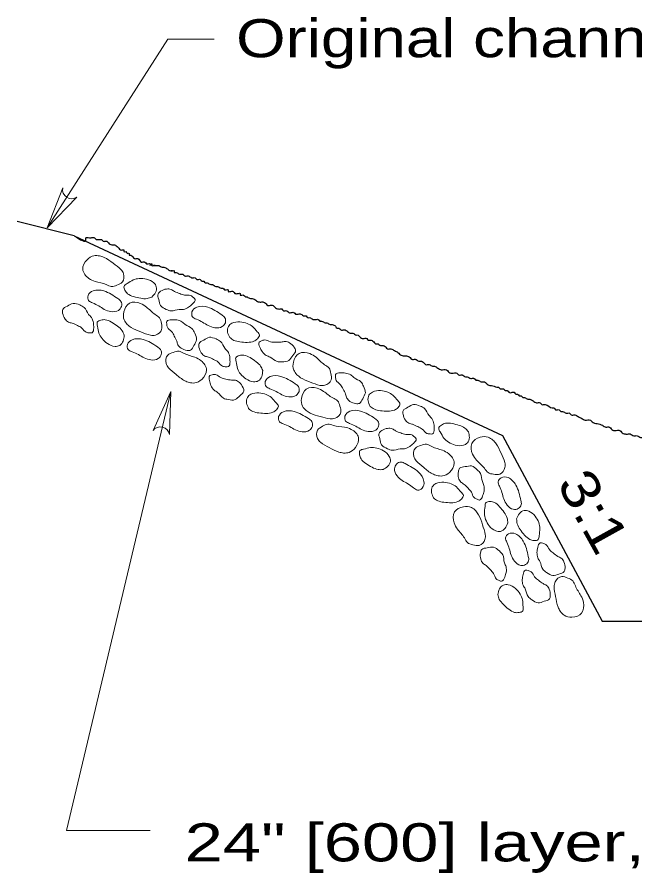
# Model space of a CAD drawing. Extents: x 1043.1 to 1101.1, y 672.4 to 716.4.
# Drawn here: x 1055.748 to 1058.344, y 697.399 to 700.994 of the extents above; entities that cross this region are included whole.
import ezdxf

# ---------------------------------------------------------------- set-up
doc = ezdxf.new("R2010")
doc.units = 0
doc.header["$LTSCALE"] = 0.064
doc.layers.add('1', color=7, linetype='Continuous', lineweight=13)

msp = doc.modelspace()

# ---------------------------------------------------------------- linework, layer by layer
at = {"layer": '1', "lineweight": 25}
for p, q in [((1055.98842, 700.07575), (1055.7485, 700.13575)), ((1055.98842, 700.07575), (1057.7875, 699.23625)), ((1057.7875, 699.23625), (1058.20733, 698.45675)), ((1058.20733, 698.45675), (1060.30633, 698.45675))]:
    msp.add_line(p, q, dxfattribs=at)
at = {"layer": '1'}
for points in [[(1055.87483, 700.10833), (1056.3815, 700.90108), (1056.57592, 700.90108)], [(1055.99958, 700.23808), (1055.87483, 700.10833), (1055.94008, 700.27608), (1055.94017, 700.276)], [(1056.39492, 699.42058), (1055.95592, 697.57708), (1056.3075, 697.57708)], [(1056.31975, 699.25708), (1056.39492, 699.42058), (1056.38842, 699.24067), (1056.38833, 699.24075)]]:
    msp.add_lwpolyline(points, dxfattribs=at)
for centre, start, end in [((1055.97764, 700.26913), 169.50421, 305.33034), ((1056.35067, 699.23493), 8.69329, 144.51942)]:
    msp.add_arc(centre, 0.03811, start, end, dxfattribs=at)
at = {"layer": '1', "lineweight": 25}
for points in [[(1055.98842, 700.07575), (1056.03742, 700.05975), (1056.03742, 700.067), (1056.052, 700.067), (1056.05933, 700.067), (1056.07383, 700.067), (1056.08108, 700.05975), (1056.08842, 700.05975), (1056.09575, 700.05975), (1056.103, 700.05975), (1056.11033, 700.05242), (1056.12492, 700.05242), (1056.13208, 700.04508), (1056.14658, 700.03783), (1056.15392, 700.03783), (1056.1685, 700.0305), (1056.17583, 700.02325), (1056.18308, 700.01592), (1056.19042, 700.01592), (1056.19758, 700.01592), (1056.19758, 700.00875), (1056.20492, 700.00875), (1056.21225, 700.00142), (1056.2195, 700.00142), (1056.2195, 699.99408), (1056.22683, 699.99408), (1056.23408, 699.98683), (1056.24142, 699.9795), (1056.24875, 699.9795), (1056.256, 699.9795), (1056.26325, 699.97233), (1056.2705, 699.965), (1056.28508, 699.965), (1056.29242, 699.95775), (1056.29975, 699.95775), (1056.307, 699.95775), (1056.307, 699.95042), (1056.31433, 699.95775), (1056.31433, 699.95042), (1056.31433, 699.95775), (1056.31433, 699.95042), (1056.32158, 699.95042), (1056.32883, 699.95042), (1056.32158, 699.95042), (1056.32883, 699.95042), (1056.336, 699.95042), (1056.34333, 699.95042), (1056.35792, 699.94308), (1056.36525, 699.94308), (1056.37983, 699.93583), (1056.39433, 699.9285), (1056.40158, 699.9285), (1056.39433, 699.9285), (1056.40158, 699.9285), (1056.40892, 699.9285), (1056.40892, 699.92125), (1056.41625, 699.92125), (1056.43083, 699.91392), (1056.44542, 699.91392), (1056.45258, 699.90658), (1056.46725, 699.90658), (1056.48183, 699.89933), (1056.48908, 699.89933), (1056.49642, 699.89933), (1056.50375, 699.892), (1056.51092, 699.892), (1056.51825, 699.892), (1056.5255, 699.88475), (1056.53283, 699.88475), (1056.54008, 699.87742), (1056.54733, 699.87742), (1056.56192, 699.87008), (1056.56925, 699.87008), (1056.58375, 699.86283), (1056.591, 699.86283), (1056.60558, 699.8555), (1056.61292, 699.8555), (1056.62025, 699.84825), (1056.6275, 699.84825), (1056.63475, 699.84825), (1056.63475, 699.84092), (1056.642, 699.84092), (1056.65658, 699.84092), (1056.66392, 699.83358), (1056.6785, 699.83358), (1056.68583, 699.83358), (1056.68583, 699.82633), (1056.69308, 699.82633), (1056.70033, 699.82633), (1056.70758, 699.81908), (1056.71492, 699.81908)], [(1056.71492, 699.81908), (1056.7295, 699.81183), (1056.73683, 699.81183), (1056.75133, 699.8045), (1056.76583, 699.79725), (1056.78042, 699.79725), (1056.795, 699.78992), (1056.80233, 699.78258), (1056.80958, 699.78258), (1056.82408, 699.78258), (1056.83142, 699.77533), (1056.846, 699.768), (1056.85333, 699.768), (1056.86058, 699.768), (1056.86792, 699.76075), (1056.87525, 699.76075), (1056.88242, 699.76075), (1056.88975, 699.75342), (1056.90433, 699.75342), (1056.91158, 699.75342), (1056.91892, 699.74608), (1056.92625, 699.74608), (1056.94075, 699.74608), (1056.95525, 699.73883), (1056.9625, 699.73883), (1056.96983, 699.7315), (1056.97708, 699.7315), (1056.99175, 699.72425), (1057.00625, 699.72425), (1057.0135, 699.72425), (1057.02083, 699.71692), (1057.02808, 699.71692), (1057.04275, 699.70958), (1057.05, 699.70958), (1057.06458, 699.70233), (1057.07183, 699.70233), (1057.08642, 699.695), (1057.09375, 699.68775), (1057.101, 699.68775), (1057.10833, 699.68042), (1057.12292, 699.68042), (1057.13742, 699.67308), (1057.15192, 699.66583), (1057.15925, 699.66583), (1057.17383, 699.6585), (1057.18108, 699.6585), (1057.18842, 699.65125), (1057.20292, 699.64392), (1057.2175, 699.64392), (1057.22483, 699.63675), (1057.23208, 699.63675), (1057.24675, 699.62942), (1057.25392, 699.62208), (1057.26125, 699.62208), (1057.27583, 699.61483), (1057.28308, 699.61483), (1057.29775, 699.6075), (1057.305, 699.60025), (1057.3195, 699.60025), (1057.33408, 699.59292), (1057.34858, 699.58558), (1057.35592, 699.57833), (1057.3705, 699.571), (1057.385, 699.571), (1057.39958, 699.56375), (1057.40692, 699.55642), (1057.4215, 699.55642), (1057.43608, 699.54908), (1057.44333, 699.54908), (1057.45792, 699.54183), (1057.46525, 699.5345), (1057.47983, 699.5345), (1057.49442, 699.52725), (1057.50175, 699.52725), (1057.51625, 699.51992), (1057.53083, 699.51258), (1057.55258, 699.51258), (1057.55992, 699.50533), (1057.57442, 699.498), (1057.59633, 699.498), (1057.60358, 699.49075), (1057.61825, 699.49075), (1057.63275, 699.48342), (1057.64, 699.48342), (1057.65458, 699.47625), (1057.66925, 699.47625), (1057.6765, 699.46892), (1057.68383, 699.46892), (1057.69833, 699.46158), (1057.71292, 699.46158), (1057.72025, 699.45433)], [(1057.72025, 699.45433), (1057.73483, 699.447), (1057.74208, 699.447), (1057.76383, 699.43975), (1057.77108, 699.43975), (1057.77842, 699.43242), (1057.793, 699.43242), (1057.80033, 699.42508), (1057.80758, 699.42508), (1057.81483, 699.41783), (1057.82942, 699.41783), (1057.83675, 699.41783), (1057.844, 699.4105), (1057.85133, 699.4105), (1057.85858, 699.40325), (1057.86592, 699.40325), (1057.87325, 699.39592), (1057.88042, 699.39592), (1057.895, 699.38858), (1057.90233, 699.38858), (1057.91692, 699.38133), (1057.9315, 699.374), (1057.946, 699.374), (1057.95333, 699.36675), (1057.96783, 699.36675), (1057.997, 699.35208), (1058.00425, 699.35208), (1058.0115, 699.34483), (1058.02608, 699.34483), (1058.03342, 699.3375), (1058.04075, 699.3375), (1058.05533, 699.33025), (1058.06983, 699.33025), (1058.07708, 699.32292), (1058.09175, 699.32292), (1058.10633, 699.31575), (1058.12092, 699.30842), (1058.13542, 699.30108), (1058.15725, 699.30108), (1058.1645, 699.29383), (1058.18633, 699.2865), (1058.20825, 699.27925), (1058.22283, 699.27192), (1058.23742, 699.27192), (1058.24475, 699.26458), (1058.25925, 699.25733), (1058.28108, 699.25733), (1058.28842, 699.25), (1058.303, 699.24275), (1058.3175, 699.24275), (1058.32483, 699.24275), (1058.33942, 699.23542), (1058.354, 699.23542), (1058.3685, 699.22808), (1058.37575, 699.22808), (1058.39033, 699.22083), (1058.40492, 699.22083), (1058.4195, 699.2135), (1058.44133, 699.20625), (1058.45592, 699.20625), (1058.4705, 699.19892), (1058.48508, 699.19892), (1058.49242, 699.19892), (1058.50692, 699.19158), (1058.5215, 699.18433), (1058.53608, 699.18433), (1058.55075, 699.177), (1058.56508, 699.177), (1058.57975, 699.16975), (1058.587, 699.16242), (1058.60158, 699.16242), (1058.60892, 699.15508), (1058.62342, 699.15508), (1058.63075, 699.14792), (1058.64533, 699.14792), (1058.65258, 699.14058), (1058.66725, 699.14058), (1058.6745, 699.13333), (1058.689, 699.13333), (1058.70358, 699.126), (1058.71092, 699.126), (1058.7255, 699.11875), (1058.74008, 699.11142), (1058.74733, 699.11142), (1058.76183, 699.10408), (1058.76908, 699.10408), (1058.78375, 699.09683), (1058.79833, 699.0895), (1058.80558, 699.0895), (1058.82008, 699.08225), (1058.83475, 699.08225)]]:
    msp.add_spline(points, degree=3, dxfattribs=at)
at = {"layer": '1'}
for points in [[(1056.09475, 699.99083), (1056.07133, 699.99133), (1056.04258, 699.97458), (1056.02442, 699.93425), (1056.04983, 699.89658), (1056.07708, 699.8835), (1056.12242, 699.87025), (1056.14442, 699.86208), (1056.16808, 699.868), (1056.19092, 699.88125), (1056.19575, 699.91608), (1056.18492, 699.93342), (1056.1515, 699.96008), (1056.114, 699.98433), (1056.09475, 699.99083)], [(1056.31458, 699.818), (1056.29475, 699.8115), (1056.26825, 699.81292), (1056.238, 699.81975), (1056.21292, 699.83208), (1056.2015, 699.84692), (1056.198, 699.86408), (1056.21075, 699.87442), (1056.23658, 699.89), (1056.2615, 699.89583), (1056.2925, 699.89333), (1056.323, 699.878), (1056.33342, 699.86083), (1056.32983, 699.83742), (1056.31458, 699.818)], [(1056.115, 699.76625), (1056.143, 699.757), (1056.17408, 699.762), (1056.18708, 699.77858), (1056.18492, 699.79925), (1056.17192, 699.81125), (1056.11292, 699.84342), (1056.0675, 699.84408), (1056.04675, 699.82433), (1056.049, 699.80308), (1056.06533, 699.79342), (1056.115, 699.76625)], [(1056.46933, 699.775), (1056.48558, 699.78883), (1056.49608, 699.80742), (1056.48933, 699.8155), (1056.478, 699.82433), (1056.45242, 699.82592), (1056.43175, 699.83233), (1056.40983, 699.84142), (1056.39542, 699.85), (1056.37633, 699.85175), (1056.3515, 699.84208), (1056.34083, 699.83175), (1056.3435, 699.80775), (1056.35133, 699.78208), (1056.3755, 699.76633), (1056.39583, 699.75975), (1056.4295, 699.766), (1056.44742, 699.76633), (1056.46933, 699.775)], [(1056.06933, 699.71), (1056.07033, 699.68875), (1056.06383, 699.66833), (1056.05325, 699.66775), (1056.03908, 699.67), (1056.02042, 699.68758), (1056.00158, 699.69842), (1055.98, 699.70825), (1055.96392, 699.71292), (1055.94975, 699.72575), (1055.93983, 699.75042), (1055.94008, 699.76533), (1055.95958, 699.77975), (1055.98358, 699.7915), (1056.01175, 699.78458), (1056.03033, 699.77425), (1056.04875, 699.74533), (1056.06075, 699.732), (1056.06933, 699.71)], [(1056.21158, 699.70275), (1056.19858, 699.72208), (1056.19708, 699.75533), (1056.22125, 699.79242), (1056.26658, 699.79142), (1056.2925, 699.77558), (1056.32825, 699.74475), (1056.34683, 699.73042), (1056.35475, 699.70733), (1056.35592, 699.681), (1056.32933, 699.65808), (1056.30892, 699.65783), (1056.26833, 699.6715), (1056.2275, 699.69008), (1056.21158, 699.70275)], [(1056.5515, 699.69792), (1056.57958, 699.68875), (1056.61075, 699.69375), (1056.62375, 699.71033), (1056.6215, 699.73092), (1056.6085, 699.74292), (1056.54942, 699.77525), (1056.50408, 699.77592), (1056.48333, 699.75608), (1056.48558, 699.73483), (1056.50192, 699.72508), (1056.5515, 699.69792)], [(1056.19833, 699.65758), (1056.18958, 699.67675), (1056.17058, 699.69508), (1056.14508, 699.71275), (1056.119, 699.72283), (1056.10042, 699.72108), (1056.08542, 699.712), (1056.0865, 699.69558), (1056.09258, 699.666), (1056.10525, 699.64392), (1056.128, 699.62283), (1056.15992, 699.61083), (1056.17958, 699.61483), (1056.19433, 699.63333), (1056.19833, 699.65758)], [(1056.419, 699.72225), (1056.39775, 699.72275), (1056.3775, 699.71583), (1056.37708, 699.70508), (1056.37983, 699.69108), (1056.39783, 699.67292), (1056.40908, 699.65433), (1056.41942, 699.63308), (1056.4245, 699.61708), (1056.43775, 699.60325), (1056.46258, 699.59392), (1056.4775, 699.59458), (1056.4915, 699.61442), (1056.50258, 699.63875), (1056.495, 699.6665), (1056.48425, 699.68492), (1056.45483, 699.70258), (1056.44125, 699.71425), (1056.419, 699.72225)], [(1056.642, 699.648), (1056.65925, 699.63608), (1056.68492, 699.62983), (1056.71583, 699.62758), (1056.7435, 699.63225), (1056.75858, 699.64308), (1056.76692, 699.65842), (1056.75775, 699.672), (1056.7375, 699.69442), (1056.71542, 699.70725), (1056.685, 699.71383), (1056.65142, 699.70792), (1056.63642, 699.6945), (1056.63308, 699.67108), (1056.642, 699.648)], [(1056.28233, 699.56233), (1056.31075, 699.55392), (1056.34158, 699.55992), (1056.35408, 699.57683), (1056.35133, 699.59733), (1056.338, 699.60892), (1056.278, 699.63958), (1056.23258, 699.63883), (1056.21242, 699.6185), (1056.21533, 699.59733), (1056.23192, 699.58808), (1056.28233, 699.56233)], [(1056.64208, 699.56733), (1056.64308, 699.546), (1056.63658, 699.52558), (1056.626, 699.525), (1056.61192, 699.52733), (1056.59325, 699.54492), (1056.57442, 699.55575), (1056.55283, 699.5655), (1056.53683, 699.57025), (1056.52258, 699.583), (1056.51275, 699.60775), (1056.513, 699.62258), (1056.5325, 699.637), (1056.55642, 699.64883), (1056.5845, 699.64192), (1056.60308, 699.6315), (1056.6215, 699.60258), (1056.6335, 699.58933), (1056.64208, 699.56733)], [(1056.77825, 699.58883), (1056.76825, 699.60775), (1056.76533, 699.62892), (1056.77475, 699.634), (1056.78842, 699.63792), (1056.81283, 699.62992), (1056.83442, 699.62825), (1056.85808, 699.6285), (1056.87475, 699.63108), (1056.89308, 699.62558), (1056.9125, 699.6075), (1056.91858, 699.59392), (1056.90708, 699.5725), (1056.89042, 699.55158), (1056.862, 699.54592), (1056.84075, 699.54733), (1056.81183, 699.56575), (1056.79533, 699.57258), (1056.77825, 699.58883)], [(1056.47158, 699.45883), (1056.49492, 699.45708), (1056.5245, 699.47233), (1056.54475, 699.5115), (1056.5215, 699.5505), (1056.495, 699.56508), (1056.45042, 699.58083), (1056.42883, 699.59008), (1056.40483, 699.58542), (1056.38133, 699.5735), (1056.37458, 699.53892), (1056.3845, 699.521), (1056.4165, 699.49258), (1056.45275, 699.4665), (1056.47158, 699.45883)], [(1056.7805, 699.50883), (1056.77183, 699.52792), (1056.75283, 699.54633), (1056.72742, 699.56392), (1056.70125, 699.574), (1056.68258, 699.57233), (1056.66758, 699.56325), (1056.66875, 699.54683), (1056.67483, 699.51725), (1056.68742, 699.495), (1056.71025, 699.474), (1056.74208, 699.462), (1056.76183, 699.466), (1056.7765, 699.48442), (1056.7805, 699.50883)], [(1056.92392, 699.49183), (1056.91092, 699.51125), (1056.90942, 699.54442), (1056.9335, 699.5815), (1056.97883, 699.5805), (1057.00475, 699.56475), (1057.04042, 699.53383), (1057.05908, 699.5195), (1057.067, 699.49642), (1057.06825, 699.47025), (1057.0415, 699.44733), (1057.02108, 699.447), (1056.9805, 699.46075), (1056.93975, 699.47933), (1056.92392, 699.49183)], [(1056.56258, 699.44675), (1056.55675, 699.46725), (1056.55833, 699.48842), (1056.5685, 699.4915), (1056.58283, 699.4925), (1056.60492, 699.47975), (1056.62575, 699.47358), (1056.649, 699.469), (1056.66575, 699.46825), (1056.68258, 699.459), (1056.69792, 699.43725), (1056.701, 699.42275), (1056.68542, 699.40408), (1056.66475, 699.38708), (1056.63583, 699.38742), (1056.61533, 699.39325), (1056.59075, 699.41708), (1056.576, 699.42733), (1056.56258, 699.44675)], [(1057.12825, 699.49892), (1057.10692, 699.49942), (1057.08675, 699.4925), (1057.08633, 699.48183), (1057.089, 699.46792), (1057.107, 699.44975), (1057.11833, 699.43108), (1057.12858, 699.40983), (1057.13375, 699.39383), (1057.14683, 699.37992), (1057.17175, 699.37058), (1057.18658, 699.37133), (1057.20058, 699.39108), (1057.21175, 699.41542), (1057.20408, 699.44333), (1057.19333, 699.46175), (1057.16392, 699.47942), (1057.15033, 699.49092), (1057.12825, 699.49892)], [(1056.86142, 699.40725), (1056.88983, 699.39883), (1056.92083, 699.40483), (1056.93333, 699.42175), (1056.9305, 699.44225), (1056.91708, 699.45383), (1056.85708, 699.48442), (1056.81175, 699.48383), (1056.7915, 699.46342), (1056.79442, 699.44225), (1056.811, 699.433), (1056.86142, 699.40725)], [(1056.96292, 699.34133), (1056.948, 699.35942), (1056.94342, 699.39242), (1056.96358, 699.43158), (1057.00892, 699.435), (1057.03625, 699.42192), (1057.07483, 699.3945), (1057.09483, 699.38225), (1057.10492, 699.35992), (1057.10858, 699.33392), (1057.08433, 699.30858), (1057.064, 699.30633), (1057.02233, 699.31583), (1056.97992, 699.33042), (1056.96292, 699.34133)], [(1057.23242, 699.35892), (1057.24958, 699.34692), (1057.27533, 699.34058), (1057.30625, 699.33842), (1057.33392, 699.343), (1057.349, 699.35392), (1057.35733, 699.36933), (1057.34808, 699.38292), (1057.32792, 699.40533), (1057.30583, 699.41808), (1057.27542, 699.42475), (1057.24183, 699.41883), (1057.22683, 699.40542), (1057.2235, 699.382), (1057.23242, 699.35892)], [(1056.7215, 699.34958), (1056.73858, 699.33758), (1056.76433, 699.33133), (1056.79525, 699.32908), (1056.82292, 699.33375), (1056.83808, 699.34458), (1056.84642, 699.36), (1056.83725, 699.37358), (1056.81692, 699.396), (1056.79483, 699.40883), (1056.76442, 699.41542), (1056.73092, 699.4095), (1056.71592, 699.39608), (1056.71258, 699.37275), (1056.7215, 699.34958)], [(1057.49992, 699.28525), (1057.50092, 699.26392), (1057.49442, 699.2435), (1057.48383, 699.24292), (1057.46975, 699.24525), (1057.451, 699.26283), (1057.43225, 699.27358), (1057.41058, 699.28342), (1057.3945, 699.28808), (1057.38033, 699.30092), (1057.37042, 699.3255), (1057.37075, 699.34042), (1057.39025, 699.35483), (1057.41425, 699.36658), (1057.44233, 699.35975), (1057.46092, 699.34933), (1057.47933, 699.32042), (1057.49133, 699.30725), (1057.49992, 699.28525)], [(1056.91783, 699.26025), (1056.94608, 699.252), (1056.977, 699.25825), (1056.98942, 699.27533), (1056.98642, 699.29583), (1056.97292, 699.30725), (1056.91275, 699.33733), (1056.86742, 699.33625), (1056.84742, 699.31575), (1056.85042, 699.2945), (1056.86708, 699.2855), (1056.91783, 699.26025)], [(1057.19583, 699.2615), (1057.22425, 699.25308), (1057.25525, 699.25908), (1057.26775, 699.276), (1057.26492, 699.2965), (1057.2515, 699.30808), (1057.1915, 699.33875), (1057.14625, 699.338), (1057.126, 699.31758), (1057.12892, 699.2965), (1057.14542, 699.28733), (1057.19583, 699.2615)], [(1057.12058, 699.16275), (1057.14375, 699.16533), (1057.17008, 699.18575), (1057.18283, 699.228), (1057.15258, 699.262), (1057.124, 699.2715), (1057.07733, 699.27883), (1057.05433, 699.28392), (1057.0315, 699.27492), (1057.01075, 699.25883), (1057.0105, 699.22358), (1057.0235, 699.20783), (1057.06025, 699.18583), (1057.10075, 699.16675), (1057.12058, 699.16275)], [(1057.64458, 699.25233), (1057.63, 699.26742), (1057.60608, 699.27858), (1057.57625, 699.28683), (1057.54808, 699.28775), (1057.53125, 699.28), (1057.52, 699.26658), (1057.52642, 699.25142), (1057.54192, 699.2255), (1057.561, 699.20858), (1057.5895, 699.19625), (1057.62358, 699.19542), (1057.64092, 699.20558), (1057.64875, 699.22792), (1057.64458, 699.25233)], [(1057.39808, 699.18958), (1057.41442, 699.20342), (1057.42492, 699.222), (1057.41808, 699.23025), (1057.40683, 699.239), (1057.38125, 699.24058), (1057.3605, 699.247), (1057.33875, 699.25608), (1057.32433, 699.26475), (1057.30525, 699.26642), (1057.28042, 699.25683), (1057.26975, 699.24642), (1057.27242, 699.22233), (1057.28025, 699.19675), (1057.30442, 699.18092), (1057.32475, 699.17433), (1057.35833, 699.18058), (1057.37625, 699.18092), (1057.39808, 699.18958)], [(1057.748, 699.21708), (1057.728, 699.22908), (1057.69475, 699.22883), (1057.65892, 699.20275), (1057.66233, 699.1575), (1057.67942, 699.13258), (1057.71225, 699.09858), (1057.72733, 699.08058), (1057.75075, 699.07392), (1057.77708, 699.07408), (1057.79858, 699.10208), (1057.79783, 699.12242), (1057.78192, 699.16208), (1057.76133, 699.20183), (1057.748, 699.21708)], [(1057.28608, 699.0935), (1057.26508, 699.09342), (1057.24042, 699.10283), (1057.21383, 699.11858), (1057.19358, 699.13808), (1057.18733, 699.15558), (1057.18925, 699.173), (1057.2045, 699.179), (1057.234, 699.18583), (1057.25942, 699.18383), (1057.28825, 699.17192), (1057.3125, 699.14808), (1057.31725, 699.1285), (1057.30658, 699.10742), (1057.28608, 699.0935)], [(1057.51225, 699.068), (1057.5355, 699.06633), (1057.565, 699.0815), (1057.58533, 699.12083), (1057.562, 699.15975), (1057.53558, 699.17433), (1057.491, 699.19), (1057.46942, 699.19933), (1057.44542, 699.19458), (1057.42192, 699.18275), (1057.41525, 699.14825), (1057.42508, 699.13033), (1057.45708, 699.10192), (1057.49333, 699.07575), (1057.51225, 699.068)], [(1057.36675, 699.047), (1057.34508, 699.06725), (1057.33442, 699.09692), (1057.34275, 699.11633), (1057.36175, 699.12433), (1057.37842, 699.11858), (1057.43542, 699.08258), (1057.45792, 699.04325), (1057.45058, 699.01542), (1057.43092, 699.007), (1057.4145, 699.01683), (1057.36675, 699.047)], [(1057.71083, 699.00275), (1057.70458, 698.98242), (1057.69158, 698.96542), (1057.68142, 698.96842), (1057.66892, 698.97542), (1057.65733, 698.99825), (1057.64333, 699.01475), (1057.62633, 699.03125), (1057.61275, 699.04108), (1057.60358, 699.05792), (1057.60275, 699.0845), (1057.608, 699.0985), (1057.63125, 699.1055), (1057.65783, 699.10842), (1057.68192, 699.09242), (1057.696, 699.07633), (1057.70342, 699.04283), (1057.71025, 699.02633), (1057.71083, 699.00275)], [(1057.79308, 698.97), (1057.80733, 698.944), (1057.83358, 698.92642), (1057.85442, 698.92975), (1057.86683, 698.94633), (1057.86542, 698.96392), (1057.84433, 699.02783), (1057.81158, 699.05933), (1057.78292, 699.05892), (1057.77, 699.04183), (1057.77542, 699.02358), (1057.79308, 698.97)], [(1057.49883, 698.97442), (1057.516, 698.96242), (1057.54175, 698.95608), (1057.5725, 698.95392), (1057.60025, 698.9585), (1057.61542, 698.96942), (1057.62375, 698.98475), (1057.6145, 698.99833), (1057.59425, 699.02075), (1057.57208, 699.0335), (1057.54183, 699.04008), (1057.50825, 699.03425), (1057.49325, 699.02083), (1057.48992, 698.99742), (1057.49883, 698.97442)], [(1057.81025, 698.86892), (1057.80758, 698.88975), (1057.79508, 698.913), (1057.776, 698.93742), (1057.754, 698.95492), (1057.73592, 698.95892), (1057.71892, 698.95475), (1057.71492, 698.93883), (1057.71192, 698.90875), (1057.71725, 698.88375), (1057.73258, 698.85675), (1057.75942, 698.83575), (1057.77942, 698.83358), (1057.799, 698.84683), (1057.81025, 698.86892)], [(1057.67608, 698.92), (1057.6575, 698.934), (1057.62442, 698.93733), (1057.586, 698.91508), (1057.58458, 698.86983), (1057.59892, 698.84308), (1057.62792, 698.80592), (1057.641, 698.78642), (1057.66358, 698.77733), (1057.68992, 698.77475), (1057.71433, 698.80025), (1057.71558, 698.82042), (1057.70408, 698.86158), (1057.68783, 698.90333), (1057.67608, 698.92)], [(1057.8475, 698.88633), (1057.84992, 698.8655), (1057.86208, 698.842), (1057.88092, 698.81742), (1057.90275, 698.79983), (1057.92092, 698.7955), (1057.93792, 698.7995), (1057.94208, 698.81542), (1057.94542, 698.84533), (1057.9405, 698.87042), (1057.92533, 698.8975), (1057.89875, 698.91892), (1057.87875, 698.92133), (1057.859, 698.90833), (1057.8475, 698.88633)], [(1057.82408, 698.73433), (1057.83833, 698.70833), (1057.86458, 698.69075), (1057.88542, 698.694), (1057.89783, 698.71058), (1057.89642, 698.72825), (1057.87533, 698.79225), (1057.84258, 698.82358), (1057.81392, 698.82325), (1057.801, 698.80625), (1057.80642, 698.788), (1057.82408, 698.73433)], [(1057.93283, 698.74558), (1057.93625, 698.76675), (1057.94683, 698.78525), (1057.95725, 698.78358), (1057.97058, 698.7785), (1057.98508, 698.75733), (1058.00125, 698.74292), (1058.02033, 698.72883), (1058.03508, 698.72092), (1058.04642, 698.70542), (1058.05092, 698.67908), (1058.0475, 698.66458), (1058.02542, 698.6545), (1057.9995, 698.64825), (1057.9735, 698.66075), (1057.95742, 698.67475), (1057.94542, 698.70683), (1057.93658, 698.72233), (1057.93283, 698.74558)], [(1057.80375, 698.66158), (1057.7975, 698.64125), (1057.7845, 698.62433), (1057.77433, 698.62733), (1057.76183, 698.63433), (1057.75025, 698.65708), (1057.73633, 698.67358), (1057.71933, 698.69008), (1057.70575, 698.7), (1057.69658, 698.71683), (1057.69575, 698.74342), (1057.701, 698.75742), (1057.72425, 698.76442), (1057.75075, 698.76733), (1057.77483, 698.75133), (1057.78892, 698.73525), (1057.79633, 698.70175), (1057.80308, 698.68525), (1057.80375, 698.66158)], [(1057.87083, 698.63092), (1057.87425, 698.65192), (1057.88483, 698.67042), (1057.89533, 698.66883), (1057.90875, 698.66375), (1057.92325, 698.64258), (1057.93933, 698.62825), (1057.95833, 698.61408), (1057.97308, 698.60625), (1057.98442, 698.59075), (1057.98892, 698.56442), (1057.9855, 698.54992), (1057.96342, 698.53983), (1057.93758, 698.53342), (1057.91158, 698.546), (1057.8955, 698.56), (1057.8835, 698.59208), (1057.87458, 698.60758), (1057.87083, 698.63092)], [(1058.03075, 698.49792), (1058.04733, 698.4815), (1058.07975, 698.47375), (1058.12075, 698.49025), (1058.12833, 698.535), (1058.11783, 698.56333), (1058.09425, 698.60433), (1058.08383, 698.62542), (1058.06258, 698.6375), (1058.037, 698.64375), (1058.00942, 698.62183), (1058.00525, 698.60183), (1058.011, 698.5595), (1058.02142, 698.51592), (1058.03075, 698.49792)], [(1057.76833, 698.56808), (1057.77458, 698.54808), (1057.791, 698.52742), (1057.81408, 698.50675), (1057.83883, 698.49342), (1057.8575, 698.49275), (1057.8735, 698.49983), (1057.87458, 698.51625), (1057.87225, 698.54633), (1057.86258, 698.57), (1057.84258, 698.59383), (1057.81242, 698.60975), (1057.79233, 698.60833), (1057.77542, 698.59183), (1057.76833, 698.56808)]]:
    msp.add_spline(points, degree=3, dxfattribs=at)

# ---------------------------------------------------------------- texts
for s, width, p in [('Original channel', 1.25, (1056.66867, 700.82533)), ('24" [600] layer, CMS 207,', 1.35, (1056.45258, 697.44742))]:
    msp.add_text(s, height=0.16, dxfattribs=dict(at, width=width)).set_placement(p)
at = {"layer": '1', "width": 1.2}
msp.add_text('3:1', height=0.16, rotation=299.006, dxfattribs=at).set_placement((1058.01375, 699.035))

doc.saveas('drawing.dxf')
